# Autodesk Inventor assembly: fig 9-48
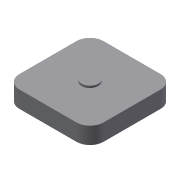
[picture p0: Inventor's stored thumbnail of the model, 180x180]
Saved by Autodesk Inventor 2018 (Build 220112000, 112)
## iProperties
Created: 2013-07
Part Number: fig 9-48
Document SubType Name: Assembly
Designer: CADCIM
Author: CADCIM
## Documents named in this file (3)
- E:\_Deepak\Inventor\Autodesk Inventor_2017_Project\Resources\Inventor_2018_Part\c09_Inv_2018\c09_inv_2018_prt\fig 9-48.iam
- E:\_Deepak\Inventor\Autodesk Inventor_2017_Project\Resources\Inventor_2018_Part\c09_Inv_2018\c09_inv_2018_prt\17 (1).ipt
- E:\_Deepak\Inventor\Autodesk Inventor_2017_Project\Resources\Inventor_2018_Part\c09_Inv_2018\c09_inv_2018_prt\18.ipt
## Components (2 placed, 2 different names)
1. 17 (1):1 — Planar:1
2. 18:1 — Planar:1
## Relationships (1: PlanarJoint 1)
- Planar:1: 17 (1):1 ↔ 18:1
